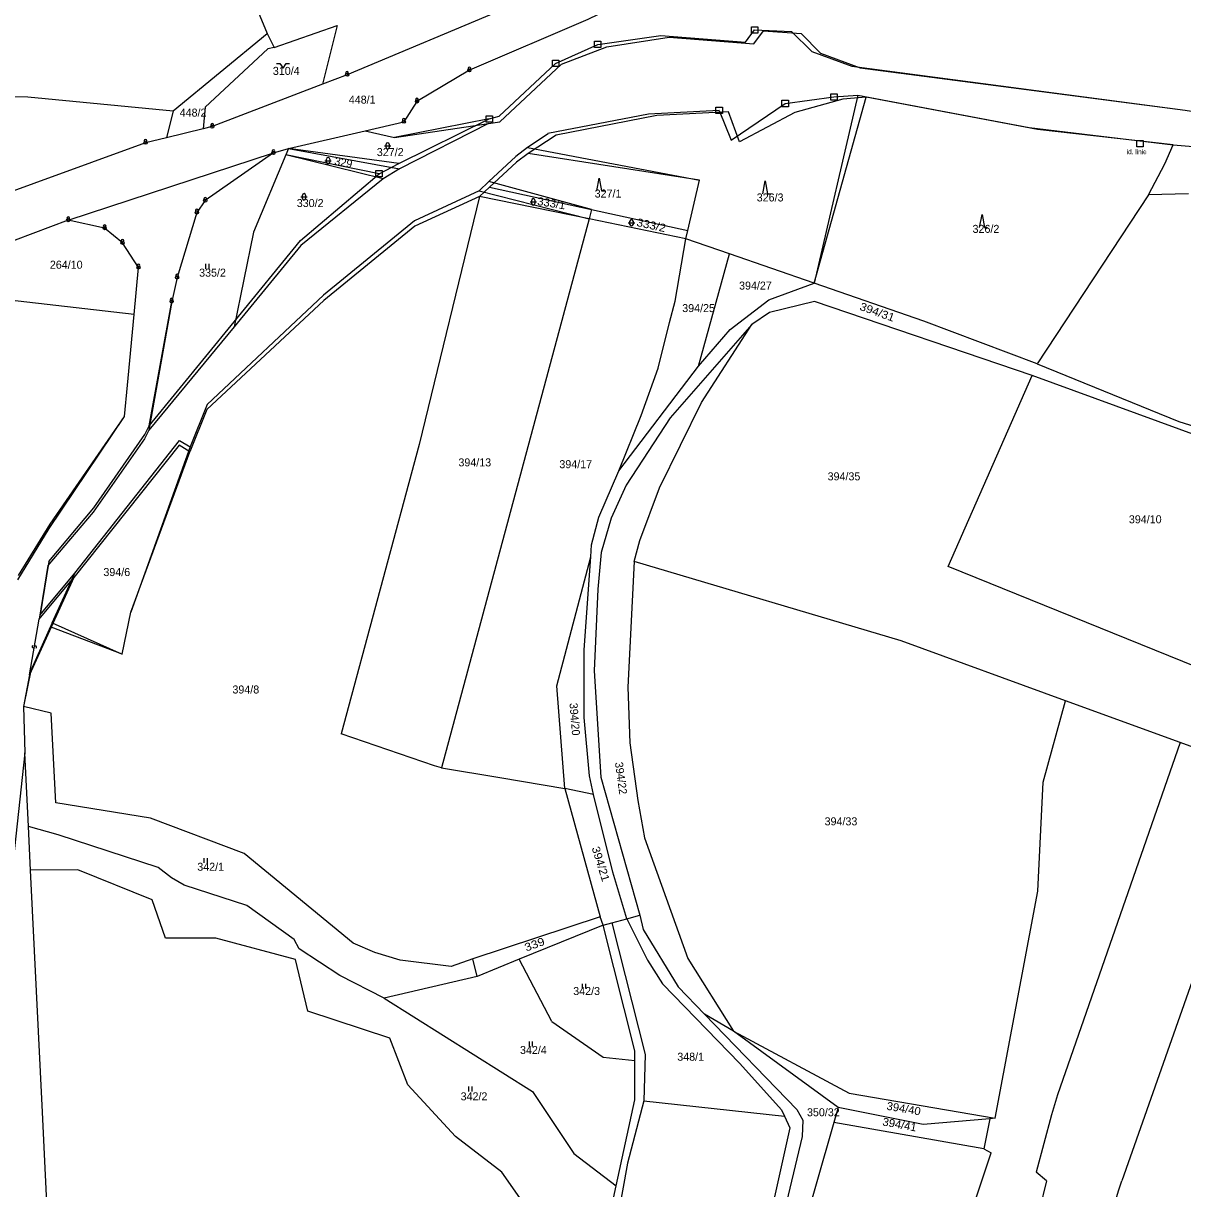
# Model space of a CAD drawing. Extents: x -680102 to -677253, y -1007548 to -1006096.
# Drawn here: x -678281.3 to -677919.2, y -1006685.2 to -1006321 of the extents above; entities that cross this region are included whole.
import ezdxf

# ---------------------------------------------------------------- set-up
doc = ezdxf.new("R2010")
doc.units = 0
for name, color, linetype, lineweight in [('1', 7, 'Continuous', 25), ('11', 7, 'Continuous', 25), ('24', 7, 'Continuous', 25), ('25', 7, 'Continuous', 25), ('35', 7, 'Continuous', 25), ('4', 7, 'Continuous', 25)]:
    doc.layers.add(name, color=color, linetype=linetype, lineweight=lineweight)
doc.layers.add('18', color=7, linetype='Continuous')

msp = doc.modelspace()

# ---------------------------------------------------------------- linework, layer by layer
at = {"layer": '1'}
for p, q in [((-678209.48, -1006313.6), (-678205.1, -1006324.25)), ((-678130.46, -1006316.3), (-678180.18, -1006337.1)), ((-677964.57, -1006354.22), (-678018.03, -1006344.08)), ((-678222.28, -1006353.31), (-678225.12, -1006354)), ((-678174.55, -1006354.6), (-678165.35, -1006356.69)), ((-678136.03, -1006352.33), (-678163.82, -1006366.54)), ((-677922.14, -1006358.97), (-677964.57, -1006354.22)), ((-678203.18, -1006361.53), (-678198.51, -1006360.2)), ((-678168.94, -1006369.68), (-678199.31, -1006362.12)), ((-677922.14, -1006358.97), (-677854.94, -1006365.15)), ((-678138.82, -1006375.13), (-678159.02, -1006384.43)), ((-678138.82, -1006375.13), (-678157.68, -1006452.66)), ((-678267.26, -1006382.54), (-678322.15, -1006403.3)), ((-678255.9, -1006385.05), (-678267.26, -1006382.54)), ((-678250.31, -1006389.6), (-678255.9, -1006385.05)), ((-678159.02, -1006384.43), (-678187.49, -1006407.61)), ((-678245.33, -1006397.33), (-678250.31, -1006389.6)), ((-678070.46, -1006428.16), (-678060.76, -1006393.07)), ((-678246.7, -1006412.02), (-678245.33, -1006397.33)), ((-678246.7, -1006412.02), (-678322.15, -1006403.3)), ((-677964.64, -1006427.47), (-678000, -1006414.15)), ((-678273.17, -1006478.9), (-678249.68, -1006443.91)), ((-678232.67, -1006452.8), (-678265.47, -1006494.18)), ((-678229.32, -1006454.88), (-678232.67, -1006452.8)), ((-678157.68, -1006452.66), (-678182.07, -1006543.07)), ((-678247.7, -1006505.06), (-678229.32, -1006454.88)), ((-678088.72, -1006482.62), (-678082.58, -1006466.13)), ((-678283.05, -1006494.88), (-678273.17, -1006478.9)), ((-678090.56, -1006489.19), (-678088.72, -1006482.62)), ((-678114.62, -1006528.01), (-678104.1, -1006487.79)), ((-678007.17, -1006513.94), (-678090.56, -1006489.19)), ((-678250.47, -1006518.1), (-678247.7, -1006505.06)), ((-678250.47, -1006518.1), (-678272.56, -1006509.72)), ((-677955.78, -1006532.68), (-678007.17, -1006513.94)), ((-677962.81, -1006558.18), (-677955.78, -1006532.68)), ((-677893.46, -1006555.36), (-677938.25, -1006682.71)), ((-678212.35, -1006580.46), (-678241.53, -1006569.42)), ((-678178.25, -1006608.44), (-678212.35, -1006580.46)), ((-678264.24, -1006585.56), (-678279.05, -1006585.61)), ((-678092.81, -1006600.82), (-678086.39, -1006613.72)), ((-678088.73, -1006599.68), (-678087.7, -1006604.13)), ((-678090.33, -1006642.05), (-678100.15, -1006602.87)), ((-678087.7, -1006604.13), (-678076.82, -1006622.09)), ((-678192.43, -1006629.65), (-678196.29, -1006613.59)), ((-678116.2, -1006632.93), (-678126.4, -1006613.49)), ((-678166.81, -1006638.09), (-678192.43, -1006629.65)), ((-678059.46, -1006635.94), (-678068.51, -1006630.68)), ((-678161.19, -1006652.74), (-678166.81, -1006638.09)), ((-678026.83, -1006659.74), (-678059.46, -1006635.94)), ((-678146.27, -1006668.81), (-678161.19, -1006652.74)), ((-678087.54, -1006657.75), (-678043.59, -1006662.46)), ((-678044.46, -1006660.54), (-678043.59, -1006662.46)), ((-678000.29, -1006665.11), (-678026.83, -1006659.74)), ((-678043.59, -1006662.46), (-678041.86, -1006666.11)), ((-677979.41, -1006663.29), (-677981.26, -1006672.68)), ((-678041.86, -1006666.11), (-678061.39, -1006753.42)), ((-677981.26, -1006672.68), (-678028.18, -1006664.46)), ((-677989.01, -1006703.77), (-677979.06, -1006673.97)), ((-677981.26, -1006672.68), (-677979.06, -1006673.97)), ((-678092.6, -1006677.21), (-678107.32, -1006758.39)), ((-677961.73, -1006682.75), (-677965, -1006680.02))]:
    msp.add_line(p, q, dxfattribs=at)
for points in [[(-677896.13, -1006293.68), (-677958.9, -1006269.98), (-678025.7, -1006241.54), (-678034.06, -1006233.78), (-678057.89, -1006270.97), (-678078.93, -1006300.97), (-678089.46, -1006312.29), (-678105.02, -1006319.82), (-678141.98, -1006335.73), (-678158.36, -1006345.46), (-678162.46, -1006351.78)], [(-678203, -1006328.63), (-678183.32, -1006321.76), (-678187.9, -1006340.07)], [(-678234.53, -1006348.36), (-678205.1, -1006324.25), (-678203, -1006328.63), (-678204.88, -1006328.99), (-678224.49, -1006347.26), (-678225.12, -1006354), (-678236.56, -1006356.81)], [(-678132.43, -1006351.8), (-678113.24, -1006333.77), (-678099.09, -1006328.36), (-678079.6, -1006325.34), (-678053.15, -1006327.44), (-678050.16, -1006323.4), (-678038.33, -1006324.2), (-678032.36, -1006330.42), (-678019.89, -1006334.95), (-677918.4, -1006348.18), (-677863.38, -1006356.93)], [(-678180.18, -1006337.1), (-678187.9, -1006340.07), (-678222.28, -1006353.31)], [(-678318.91, -1006343.87), (-678279.85, -1006344.02), (-678234.53, -1006348.36), (-678236.56, -1006356.81), (-678243.14, -1006358.35), (-678294.96, -1006377.2)], [(-678018.03, -1006344.08), (-678025.34, -1006344.76), (-678040.3, -1006348.88), (-678057.65, -1006358.05), (-678061.01, -1006348.73), (-678083.44, -1006349.86), (-678114.88, -1006355.95), (-678123.6, -1006361.67)], [(-678000, -1006414.15), (-678034.32, -1006402.24), (-678018.03, -1006344.08)], [(-678198.51, -1006360.2), (-678174.55, -1006354.6), (-678162.46, -1006351.78)], [(-678165.35, -1006356.69), (-678136.03, -1006352.33), (-678132.43, -1006351.8)], [(-678267.26, -1006382.54), (-678203.18, -1006361.53), (-678224.47, -1006376.45), (-678227.09, -1006380.13), (-678233.26, -1006400.47), (-678234.96, -1006407.96), (-678242.05, -1006448.18), (-678243.47, -1006450.89), (-678259.51, -1006473.8), (-678273.59, -1006490.49), (-678276.38, -1006507.2), (-678265.47, -1006494.18)], [(-678198.51, -1006360.2), (-678199.31, -1006362.12), (-678209.39, -1006386.33)], [(-678198.51, -1006360.2), (-678163.82, -1006366.54), (-678168.94, -1006369.68)], [(-678070.06, -1006370.08), (-678123.6, -1006361.67), (-678127.26, -1006364.42)], [(-677929.87, -1006374.61), (-677924.77, -1006364.95), (-677922.14, -1006358.97)], [(-678127.26, -1006364.42), (-678135.74, -1006372.28), (-678138.82, -1006375.13)], [(-678168.94, -1006369.68), (-678194.61, -1006390.45), (-678215.4, -1006415.84)], [(-678135.74, -1006372.28), (-678103.81, -1006379.22), (-678073.77, -1006385.75)], [(-678074.39, -1006388.34), (-678073.77, -1006385.75), (-678070.06, -1006370.08)], [(-678074.39, -1006388.34), (-678104.6, -1006382.15), (-678138.82, -1006375.13)], [(-677917.37, -1006374.36), (-677929.87, -1006374.61), (-677964.64, -1006427.47)], [(-678103.81, -1006379.22), (-678104.6, -1006382.15), (-678150.72, -1006553.63), (-678152.85, -1006553.07), (-678182.07, -1006543.07)], [(-678209.39, -1006386.33), (-678215.4, -1006415.84), (-678242.05, -1006448.18)], [(-678095.31, -1006460.84), (-678088.28, -1006443.53), (-678083.07, -1006428.79), (-678079.52, -1006414.56), (-678077.74, -1006407.83), (-678074.39, -1006388.34)], [(-678034.32, -1006402.24), (-678060.76, -1006393.07), (-678074.39, -1006388.34)], [(-678103.84, -1006484.04), (-678101.52, -1006475.32), (-678095.31, -1006460.84), (-678070.46, -1006428.16), (-678060.57, -1006416.67), (-678048.48, -1006407.43), (-678034.32, -1006402.24)], [(-678187.49, -1006407.61), (-678223.98, -1006441.66), (-678229.32, -1006454.88)], [(-677860.14, -1006469.84), (-677966.17, -1006431.09), (-678034.19, -1006407.98), (-678048.29, -1006411.44), (-678053.78, -1006415.18), (-678079.32, -1006444.33)], [(-678249.68, -1006443.91), (-678248.77, -1006434.15), (-678248.56, -1006431.87), (-678246.7, -1006412.02)], [(-678082.58, -1006466.13), (-678069.44, -1006439.48), (-678053.78, -1006415.18)], [(-677964.64, -1006427.47), (-677920.4, -1006445.43), (-677888.93, -1006455.2), (-677856.48, -1006467.11), (-677835.11, -1006451.68)], [(-677893.46, -1006530.84), (-677992.47, -1006490.71), (-677966.17, -1006431.09)], [(-678079.32, -1006444.33), (-678092.98, -1006465.3), (-678097.72, -1006475.69), (-678100.8, -1006486.38), (-678101.88, -1006497.89), (-678102.96, -1006523.31), (-678100.9, -1006556.53), (-678088.73, -1006599.68)], [(-678106.13, -1006516.77), (-678104.1, -1006487.79), (-678103.84, -1006484.04)], [(-678090.56, -1006489.19), (-678092.52, -1006528.43), (-678091.86, -1006545.87), (-678089.37, -1006563.85), (-678087.25, -1006575.49), (-678073.74, -1006613.25), (-678059.46, -1006635.94), (-678023.33, -1006655.32), (-677977.75, -1006663.14)], [(-678265.47, -1006494.18), (-678272.56, -1006509.72), (-678279.33, -1006524.56)], [(-678092.81, -1006600.82), (-678097.19, -1006586.22), (-678103.21, -1006562.02), (-678104.45, -1006556.12), (-678106.14, -1006537.95), (-678106.13, -1006516.77)], [(-678279.33, -1006524.56), (-678281.26, -1006534.47), (-678280.85, -1006548.98), (-678285.21, -1006589.54)], [(-678103.21, -1006562.02), (-678112.16, -1006560.07), (-678114.62, -1006528.01)], [(-677899.65, -1006553.15), (-677920.01, -1006545.73), (-677955.78, -1006532.68)], [(-678241.53, -1006569.42), (-678271.19, -1006564.62), (-678272.58, -1006536.6), (-678281.26, -1006534.47)], [(-677920.01, -1006545.73), (-677958.3, -1006655.79), (-677960.2, -1006662.13), (-677965, -1006680.02)], [(-678279.05, -1006585.61), (-678279.72, -1006571.96), (-678280.85, -1006548.98)], [(-678150.72, -1006553.63), (-678132.51, -1006556.69), (-678112.16, -1006560.07), (-678101.09, -1006600.24)], [(-677977.75, -1006663.14), (-677964.46, -1006592.18), (-677962.81, -1006558.18)], [(-678139.59, -1006618.83), (-678168.59, -1006625.68), (-678182.49, -1006618.51), (-678195.19, -1006610.19), (-678196.66, -1006607.32), (-678211.53, -1006596.68), (-678231.06, -1006590.36), (-678235.04, -1006588.01), (-678239.14, -1006584.8), (-678270.4, -1006574.57), (-678279.72, -1006571.96)], [(-678273.4, -1006700.49), (-678275.33, -1006661.29), (-678279.05, -1006585.61)], [(-678236.94, -1006606.87), (-678241.07, -1006594.89), (-678264.24, -1006585.56)], [(-678100.15, -1006602.87), (-678101.09, -1006600.24), (-678140.87, -1006613.34)], [(-678100.15, -1006602.87), (-678097.45, -1006602.12), (-678087.12, -1006643.24)], [(-678097.45, -1006602.12), (-678092.81, -1006600.82), (-678088.73, -1006599.68)], [(-678100.15, -1006602.87), (-678126.4, -1006613.49), (-678139.59, -1006618.83)], [(-678196.29, -1006613.59), (-678221.13, -1006606.89), (-678236.94, -1006606.87)], [(-678139.59, -1006618.83), (-678140.87, -1006613.34), (-678147.68, -1006615.69), (-678163.55, -1006613.74), (-678171.46, -1006611.33), (-678178.25, -1006608.44)], [(-678086.39, -1006613.72), (-678081.62, -1006621.11), (-678057.53, -1006646.06), (-678044.46, -1006660.54)], [(-678076.82, -1006622.09), (-678068.51, -1006630.68), (-678039.74, -1006660.4)], [(-678168.59, -1006625.68), (-678122.32, -1006654.79), (-678109.34, -1006674.12), (-678096.1, -1006684.25)], [(-678116.2, -1006632.93), (-678100.2, -1006644.03), (-678090.32, -1006645.06)], [(-678101.85, -1006710.81), (-678096.1, -1006684.25), (-678090.29, -1006657.44), (-678090.32, -1006645.06), (-678090.33, -1006642.05)], [(-678087.12, -1006643.24), (-678087.54, -1006657.75), (-678092.6, -1006677.21)], [(-678039.74, -1006660.4), (-678037.81, -1006663.8), (-678038, -1006668.86)], [(-678026.83, -1006659.74), (-678028.18, -1006664.46), (-678039.17, -1006702.97)], [(-677977.75, -1006663.14), (-677979.41, -1006663.29), (-678000.29, -1006665.11)], [(-678117.66, -1006700.24), (-678131.87, -1006679.97), (-678146.27, -1006668.81)], [(-678038, -1006668.86), (-678045.75, -1006701.17), (-678054.2, -1006736.3)], [(-677961.73, -1006682.75), (-677968.34, -1006709.62), (-677976.77, -1006738.82), (-677984.36, -1006766.34), (-678000.82, -1006824.88), (-678012.04, -1006873.51), (-678018.16, -1006910.34), (-678018.27, -1006918.46)], [(-677966.9, -1006777.33), (-677939.1, -1006685.51), (-677938.25, -1006682.71)]]:
    msp.add_lwpolyline(points, dxfattribs=at)
at = {"layer": '11'}
for p, q in [((-678055.78, -1006326.94), (-678052.89, -1006323.12)), ((-678115.07, -1006333.55), (-678101.88, -1006327.62)), ((-678034.98, -1006329.89), (-678022.51, -1006334.41)), ((-678022.51, -1006334.41), (-677918.4, -1006348.18)), ((-678020.64, -1006343.54), (-678034.32, -1006402.24)), ((-678135.76, -1006350.92), (-678165.35, -1006356.69)), ((-678123.78, -1006359.86), (-678070.06, -1006370.08)), ((-678103.81, -1006379.22), (-678135.88, -1006370.51)), ((-678272.25, -1006508.4), (-678265.21, -1006492.84)), ((-678272.25, -1006508.4), (-678250.47, -1006518.1))]:
    msp.add_line(p, q, dxfattribs=at)
for points in [[(-678101.88, -1006327.62), (-678082.23, -1006324.86), (-678055.78, -1006326.94)], [(-678052.89, -1006323.12), (-678041.39, -1006323.57), (-678034.98, -1006329.89)], [(-678163.98, -1006364.86), (-678135.76, -1006350.92), (-678132.64, -1006350.02), (-678115.07, -1006333.55)], [(-678043.36, -1006346.1), (-678028.13, -1006344.03), (-678020.64, -1006343.54)], [(-678020.64, -1006343.54), (-677967.17, -1006353.62), (-677922.14, -1006358.97)], [(-678063.96, -1006348.27), (-678060.24, -1006357.55), (-678043.36, -1006346.1)], [(-678063.96, -1006348.27), (-678086.04, -1006349.39), (-678117.48, -1006355.51)], [(-678117.41, -1006355.53), (-678123.78, -1006359.86), (-678127.43, -1006362.62), (-678135.88, -1006370.51), (-678138.95, -1006373.37), (-678104.6, -1006382.15)], [(-678241.94, -1006446.76), (-678215.4, -1006414.33), (-678194.69, -1006388.87), (-678170.18, -1006368.03), (-678199.31, -1006362.12)], [(-678170.18, -1006368.03), (-678163.98, -1006364.86), (-678198.51, -1006360.2)], [(-678138.95, -1006373.37), (-678159.12, -1006382.74), (-678187.52, -1006406.01), (-678223.89, -1006440.18), (-678229.19, -1006453.42)], [(-678273.34, -1006489.17), (-678259.32, -1006472.44), (-678243.35, -1006449.47), (-678241.94, -1006446.76), (-678234.96, -1006407.96)], [(-678282.79, -1006493.59), (-678272.96, -1006477.58), (-678249.68, -1006443.91)], [(-678273.34, -1006489.17), (-678276.08, -1006505.89), (-678265.21, -1006492.84), (-678232.55, -1006451.35), (-678229.19, -1006453.42), (-678247.7, -1006505.06)], [(-678272.25, -1006508.4), (-678278.97, -1006523.26), (-678281.26, -1006534.47)]]:
    msp.add_lwpolyline(points, dxfattribs=at)
at = {"layer": '24'}
for centre, radius in [((-678180.18, -1006337.1), 0.5), ((-678141.98, -1006335.73), 0.5), ((-678141.98, -1006335.73), 0.022), ((-678180.18, -1006337.1), 0.022), ((-678158.36, -1006345.46), 0.5), ((-678158.36, -1006345.46), 0.022), ((-678222.28, -1006353.31), 0.5), ((-678222.28, -1006353.31), 0.022), ((-678162.46, -1006351.78), 0.5), ((-678162.46, -1006351.78), 0.022), ((-678243.14, -1006358.35), 0.5), ((-678243.14, -1006358.35), 0.022), ((-678203.18, -1006361.53), 0.5), ((-678203.18, -1006361.53), 0.022), ((-678224.47, -1006376.45), 0.5), ((-678224.47, -1006376.45), 0.022), ((-678227.09, -1006380.13), 0.5), ((-678227.09, -1006380.13), 0.022), ((-678267.26, -1006382.54), 0.5), ((-678267.26, -1006382.54), 0.022), ((-678255.9, -1006385.05), 0.5), ((-678255.9, -1006385.05), 0.022), ((-678250.31, -1006389.6), 0.5), ((-678250.31, -1006389.6), 0.022), ((-678245.33, -1006397.33), 0.5), ((-678245.33, -1006397.33), 0.022), ((-678233.26, -1006400.47), 0.5), ((-678233.26, -1006400.47), 0.022), ((-678234.96, -1006407.96), 0.5), ((-678234.96, -1006407.96), 0.022)]:
    msp.add_circle(centre, radius, dxfattribs=at)
for centre in [(-678180.181, -1006336.537), (-678141.981, -1006335.167), (-678158.361, -1006344.897), (-678162.461, -1006351.217), (-678222.281, -1006352.747), (-678243.141, -1006357.787), (-678203.181, -1006360.967), (-678224.471, -1006375.887), (-678227.091, -1006379.567), (-678267.261, -1006381.977), (-678255.901, -1006384.487), (-678250.311, -1006389.037), (-678245.331, -1006396.767), (-678233.261, -1006399.907), (-678234.961, -1006407.397)]:
    msp.add_arc(centre, 0.437, 328.35109, 209.97456, dxfattribs=at)
at = {"layer": '25'}
for p, q in [((-678168.51, -1006359.35), (-678166.51, -1006359.35)), ((-678168.01, -1006359.85), (-678168.01, -1006358.85)), ((-678167.01, -1006358.85), (-678167.01, -1006359.85)), ((-678187.1, -1006363.96), (-678185.1, -1006363.96)), ((-678186.6, -1006364.46), (-678186.6, -1006363.46)), ((-678185.6, -1006363.46), (-678185.6, -1006364.46)), ((-678194.62, -1006375.23), (-678192.62, -1006375.23)), ((-678194.12, -1006375.73), (-678194.12, -1006374.73)), ((-678193.12, -1006374.73), (-678193.12, -1006375.73)), ((-678122.52, -1006377.31), (-678122.52, -1006376.31)), ((-678121.52, -1006376.31), (-678121.52, -1006377.31)), ((-678123.02, -1006376.81), (-678121.02, -1006376.81)), ((-678092.34, -1006383.35), (-678090.34, -1006383.35)), ((-678091.84, -1006383.85), (-678091.84, -1006382.85)), ((-678090.84, -1006382.85), (-678090.84, -1006383.85)), ((-678224.307, -1006397.705), (-678224.307, -1006396.205)), ((-678223.273, -1006397.705), (-678223.273, -1006396.205)), ((-678224.827, -1006583.375), (-678224.827, -1006581.875)), ((-678223.793, -1006583.375), (-678223.793, -1006581.875)), ((-678106.697, -1006622.605), (-678106.697, -1006621.105)), ((-678105.663, -1006622.605), (-678105.663, -1006621.105)), ((-678123.257, -1006640.685), (-678123.257, -1006639.185)), ((-678122.223, -1006640.685), (-678122.223, -1006639.185)), ((-678142.137, -1006654.765), (-678142.137, -1006653.265)), ((-678141.103, -1006654.765), (-678141.103, -1006653.265))]:
    msp.add_line(p, q, dxfattribs=at)
for points in [[(-678202.17, -1006333.56), (-678201.17, -1006333.56), (-678200.17, -1006335.06), (-678199.17, -1006333.56), (-678198.17, -1006333.56)], [(-678102.22, -1006373.39), (-678101.47, -1006369.39), (-678100.72, -1006373.39), (-678099.72, -1006373.39)], [(-678050.38, -1006374.27), (-678049.63, -1006370.27), (-678048.88, -1006374.27), (-678047.88, -1006374.27)], [(-677982.62, -1006384.79), (-677981.87, -1006380.79), (-677981.12, -1006384.79), (-677980.12, -1006384.79)]]:
    msp.add_lwpolyline(points, dxfattribs=at)
for centre, radius, start, end in [((-678167.51, -1006358.85), 0.5, 0.101, 180.00143), ((-678167.51, -1006359.85), 0.5, 180.10243, 0.00286), ((-678186.1, -1006363.46), 0.5, 0.101, 180.00143), ((-678186.1, -1006364.46), 0.5, 180.10243, 0.00286), ((-678193.62, -1006374.73), 0.5, 0.101, 180.00143), ((-678193.62, -1006375.73), 0.5, 180.10243, 0.00286), ((-678122.02, -1006376.31), 0.5, 0.101, 180.00143), ((-678122.02, -1006377.31), 0.5, 180.10243, 0.00286), ((-678091.34, -1006382.85), 0.5, 0.101, 180.00143), ((-678091.34, -1006383.85), 0.5, 180.10243, 0.00286), ((-678278.212, -1006515.815), 0.367, 118.04599, 349.82334), ((-678277.488, -1006515.947), 0.368, 297.68117, 169.90926)]:
    msp.add_arc(centre, radius, start, end, dxfattribs=at)
at = {"layer": '35'}
for points in [[(-678053.89, -1006322.12), (-678051.89, -1006322.12), (-678051.89, -1006324.12), (-678053.89, -1006324.12)], [(-678102.88, -1006326.62), (-678100.88, -1006326.62), (-678100.88, -1006328.62), (-678102.88, -1006328.62)], [(-678116.07, -1006332.55), (-678114.07, -1006332.55), (-678114.07, -1006334.55), (-678116.07, -1006334.55)], [(-678029.13, -1006343.03), (-678027.13, -1006343.03), (-678027.13, -1006345.03), (-678029.13, -1006345.03)], [(-678064.96, -1006347.27), (-678062.96, -1006347.27), (-678062.96, -1006349.27), (-678064.96, -1006349.27)], [(-678044.36, -1006345.1), (-678042.36, -1006345.1), (-678042.36, -1006347.1), (-678044.36, -1006347.1)], [(-678136.76, -1006349.92), (-678134.76, -1006349.92), (-678134.76, -1006351.92), (-678136.76, -1006351.92)], [(-677933.52, -1006357.64), (-677931.52, -1006357.64), (-677931.52, -1006359.64), (-677933.52, -1006359.64)], [(-678171.18, -1006367.03), (-678169.18, -1006367.03), (-678169.18, -1006369.03), (-678171.18, -1006369.03)]]:
    msp.add_lwpolyline(points, close=True, dxfattribs=at)
at = {"layer": '4'}
msp.add_line((-678279.33, -1006524.56), (-678276.38, -1006507.2), dxfattribs=at)

# ---------------------------------------------------------------- texts
at = {"layer": '18'}
for s, p in [('310/4', (-678203.36, -1006337.16)), ('448/1', (-678179.64, -1006346.13)), ('448/2', (-678232.46, -1006350.19)), ('327/2', (-678170.89, -1006362.52)), ('327/1', (-678102.85, -1006375.47)), ('330/2', (-678195.89, -1006378.45)), ('326/3', (-678052.24, -1006376.7)), ('326/2', (-677984.83, -1006386.52)), ('264/10', (-678273, -1006397.72)), ('335/2', (-678226.39, -1006400.2)), ('394/27', (-678057.76, -1006404.24)), ('394/25', (-678075.51, -1006411.27)), ('394/13', (-678145.41, -1006459.48)), ('394/17', (-678113.88, -1006460.04)), ('394/35', (-678030.1, -1006463.84)), ('394/10', (-677936.01, -1006477.26)), ('394/6', (-678256.29, -1006493.75)), ('394/8', (-678215.99, -1006530.44)), ('394/33', (-678031.04, -1006571.63)), ('342/1', (-678226.96, -1006585.82)), ('342/3', (-678109.55, -1006624.65)), ('342/4', (-678126.17, -1006643.07)), ('348/1', (-678077.05, -1006645.18)), ('342/2', (-678144.72, -1006657.56)), ('350/32', (-678036.54, -1006662.53))]:
    msp.add_text(s, height=2.5, dxfattribs=at).set_placement(p)
for s, rotation, p in [('329', 349.003, (-678184.286, -1006365.222)), ('394/20', 274.602, (-678110.715, -1006533.473)), ('394/22', 277.902, (-678096.535, -1006552))]:
    msp.add_text(s, height=2.5, rotation=rotation, dxfattribs=at).set_placement(p)
for s, rotation, width, p in [('333/1', 350.603, 1.05, (-678120.901, -1006377.766)), ('333/2', 347.703, 1.1, (-678089.932, -1006384.348)), ('394/31', 340.403, 1.1, (-678020.305, -1006410.529)), ('394/21', 287.302, 1.1, (-678103.81, -1006578.681)), ('339', 20.1, 1.15, (-678124.201, -1006611.084)), ('394/40', 350.203, 1.05, (-678011.839, -1006660.457)), ('394/41', 349.703, 1.05, (-678013.108, -1006665.389))]:
    msp.add_text(s, height=2.5, rotation=rotation, dxfattribs=dict(at, width=width)).set_placement(p)
at = {"layer": '35', "width": 0.8}
msp.add_text('id. linie', height=1.5, dxfattribs=at).set_placement((-677936.7, -1006361.93))

doc.saveas('drawing.dxf')
